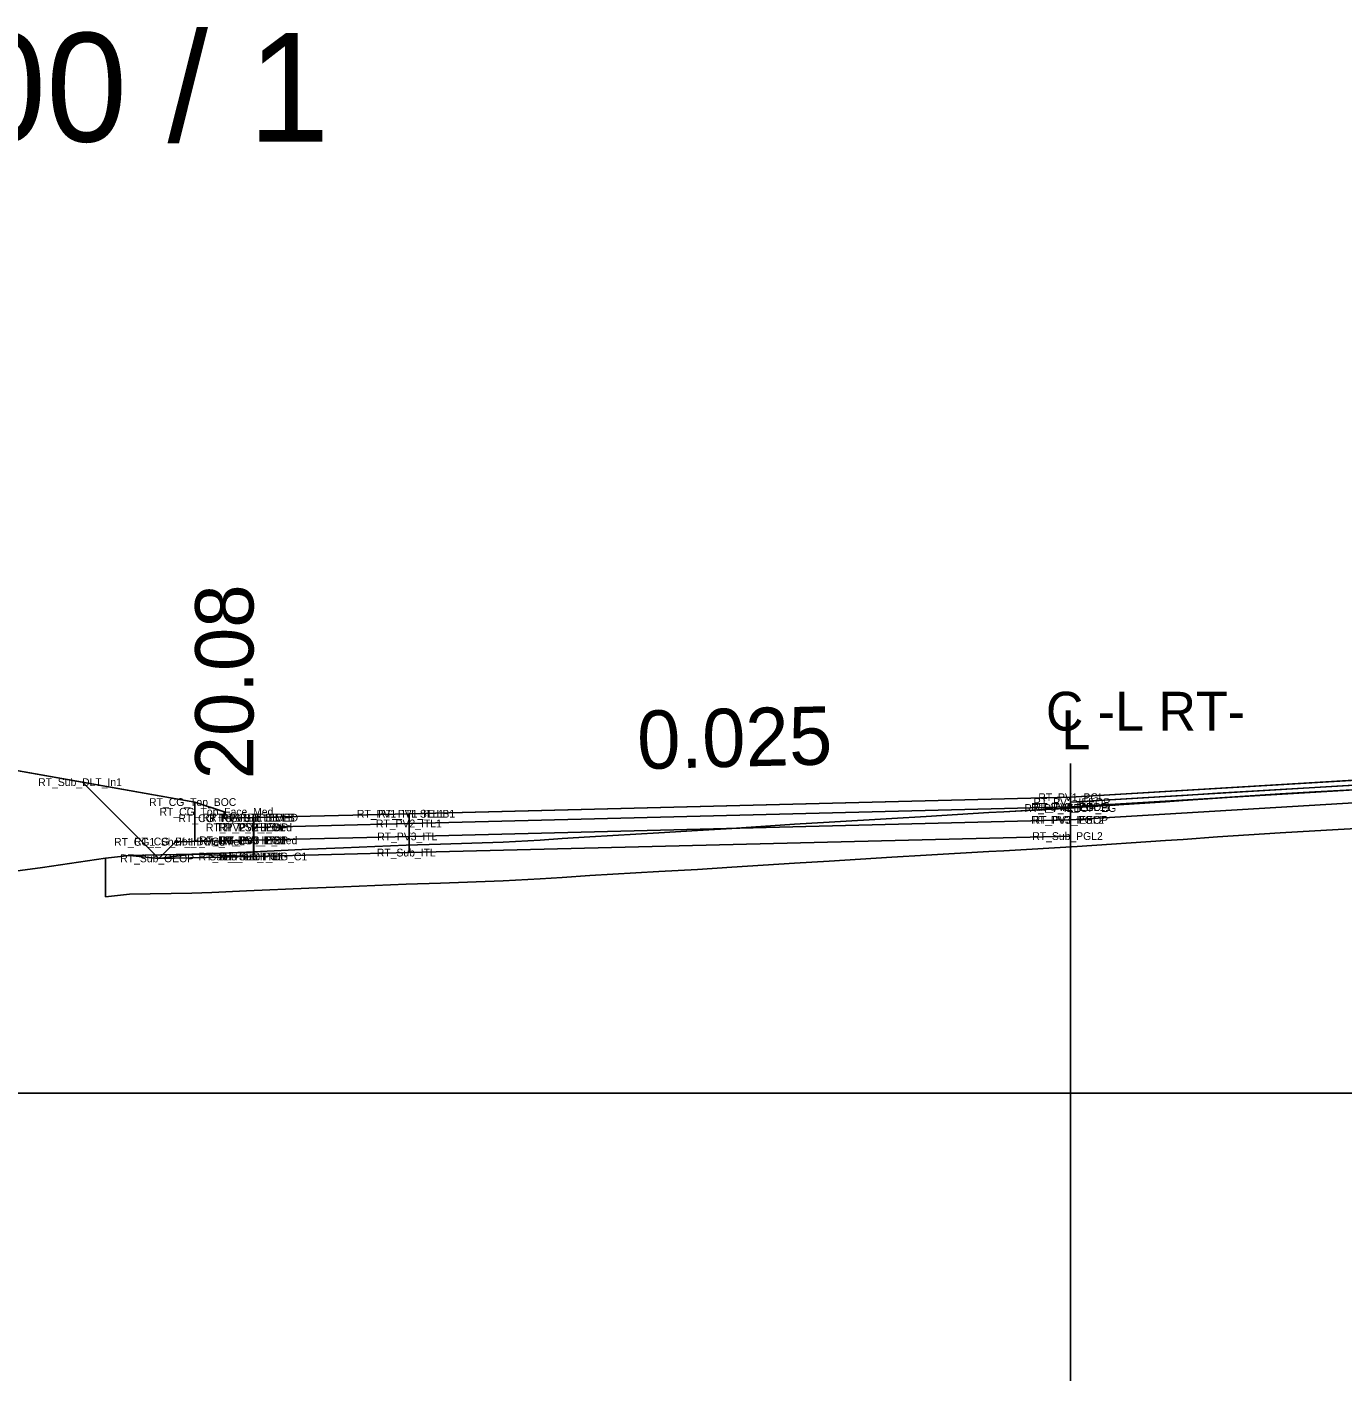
# Model space of a CAD drawing. Extents: x 2177029 to 2201446, y 59897 to 78390.
# Drawn here: x 2199245.88 to 2199279.74, y 69899.9 to 69934.76 of the extents above; entities that cross this region are included whole.
import ezdxf

# ---------------------------------------------------------------- set-up
doc = ezdxf.new("R2010")
doc.units = 0
for name, color, linetype in [('Exist CMT Pavement', 7, 'Continuous'), ('Exist Cross Section Cell', 7, 'Continuous'), ('Exist PHM Roadway Shape', 7, 'Continuous'), ('Exist XS Ground Line', 7, 'Continuous'), ('Old_Level_11', 7, 'Continuous'), ('Prop CMT Conc Surface', 7, 'Continuous'), ('Prop CMT Concrete Structures', 7, 'Continuous'), ('Prop CMT Guardrail Graphics', 7, 'Continuous'), ('Prop CMT Pvmt Course 1', 7, 'Continuous'), ('Prop CMT Pvmt Course 1 CG', 7, 'Continuous'), ('Prop CMT Pvmt Course 2', 7, 'Continuous'), ('Prop CMT Pvmt Course 2 CG', 7, 'Continuous'), ('Prop CMT Pvmt Course 3', 7, 'Continuous'), ('Prop CMT Pvmt Course 4', 7, 'Continuous'), ('Prop CMT Pvmt Surface', 7, 'Continuous'), ('Prop CMT Pvmt Wedge Surface 1', 7, 'Continuous'), ('Prop CMT Slope Grass', 7, 'Continuous'), ('Prop CMT Subgrade Earthwork', 7, 'Continuous'), ('Prop CMT Top Wall Envelope', 7, 'Continuous'), ('Prop Hatching', 7, 'Continuous'), ('Prop Horizontal Alignment', 7, 'Continuous'), ('Prop Retaining Wall', 7, 'Continuous'), ('Prop Terminator CELL', 7, 'Continuous'), ('Prop XS Side Slope Text', 7, 'Continuous'), ('Scratch_Level_0', 7, 'Continuous'), ('Scratch_Level_9', 7, 'Continuous')]:
    doc.layers.add(name, color=color, linetype=linetype)

msp = doc.modelspace()

# ---------------------------------------------------------------- linework, layer by layer
at = {"layer": 'Exist CMT Pavement'}
msp.add_line((2199272.732, 69899.904), (2199272.732, 69915.798), dxfattribs=at)
at = {"layer": 'Exist Cross Section Cell'}
msp.add_line((2199242.732, 69907.31), (2199442.732, 69907.31), dxfattribs=at)
at = {"layer": 'Exist XS Ground Line'}
msp.add_lwpolyline([(2199245.312, 69912.993), (2199246.277, 69913.12), (2199247.895, 69913.363), (2199248.517, 69913.432), (2199250.12, 69913.464), (2199250.631, 69913.479), (2199251.524, 69913.52), (2199253.131, 69913.59), (2199254.024, 69913.626), (2199255.631, 69913.695), (2199256.522, 69913.723), (2199258.131, 69913.776), (2199259.087, 69913.829), (2199259.651, 69913.866), (2199260.358, 69913.912), (2199262.138, 69914.015), (2199263.131, 69914.071), (2199264.021, 69914.129), (2199265.631, 69914.234), (2199266.52, 69914.287), (2199268.131, 69914.385), (2199269.02, 69914.438), (2199270.631, 69914.534), (2199271.019, 69914.555), (2199272.907, 69914.664), (2199275.174, 69914.816), (2199275.631, 69914.847), (2199276.518, 69914.908), (2199278.131, 69915.018), (2199279.017, 69915.067), (2199280.631, 69915.154)], dxfattribs=at)
at = {"layer": 'Prop CMT Conc Surface'}
for points in [[(2199272.732, 69914.806), (2199308.732, 69916.966)], [(2199272.732, 69914.931), (2199272.732, 69914.681), (2199272.732, 69914.681), (2199272.732, 69914.806)]]:
    msp.add_lwpolyline(points, dxfattribs=at)
at = {"layer": 'Prop CMT Concrete Structures'}
for p, q in [((2199272.732, 69914.931), (2199308.732, 69917.091)), ((2199272.732, 69914.931), (2199255.717, 69914.506)), ((2199251.707, 69914.406), (2199251.705, 69914.406)), ((2199251.715, 69914.406), (2199251.707, 69914.406)), ((2199255.717, 69914.506), (2199255.715, 69914.506))]:
    msp.add_line(p, q, dxfattribs=at)
at = {"layer": 'Prop CMT Guardrail Graphics'}
for points in [[(2199272.732, 69914.348), (2199308.732, 69916.508)], [(2199272.732, 69914.931), (2199272.732, 69914.348)]]:
    msp.add_lwpolyline(points, dxfattribs=at)
at = {"layer": 'Prop CMT Pvmt Course 1'}
for points in [[(2199272.732, 69914.681), (2199272.907, 69914.692), (2199275.174, 69914.828), (2199275.631, 69914.855), (2199276.518, 69914.909), (2199276.574, 69914.912)], [(2199276.574, 69914.912), (2199276.518, 69914.908), (2199275.631, 69914.847), (2199275.174, 69914.816), (2199272.907, 69914.664), (2199272.732, 69914.654)], [(2199272.732, 69914.654), (2199272.732, 69914.681)]]:
    msp.add_lwpolyline(points, dxfattribs=at)
at = {"layer": 'Prop CMT Pvmt Course 1 CG'}
for points in [[(2199251.715, 69913.822), (2199255.715, 69913.922)], [(2199255.715, 69913.922), (2199255.715, 69913.506)], [(2199251.715, 69913.406), (2199251.715, 69913.822)], [(2199255.715, 69913.506), (2199251.715, 69913.406)]]:
    msp.add_lwpolyline(points, dxfattribs=at)
at = {"layer": 'Prop CMT Pvmt Course 2'}
for points in [[(2199272.732, 69914.348), (2199255.715, 69913.922)], [(2199272.732, 69913.931), (2199272.732, 69914.348)], [(2199255.715, 69913.506), (2199272.732, 69913.931)], [(2199255.715, 69913.922), (2199255.715, 69913.506)], [(2199251.715, 69913.822), (2199251.705, 69913.822)], [(2199251.705, 69913.822), (2199251.705, 69913.406)], [(2199251.715, 69913.406), (2199251.715, 69913.822)], [(2199251.705, 69913.406), (2199251.715, 69913.406)]]:
    msp.add_lwpolyline(points, dxfattribs=at)
at = {"layer": 'Prop CMT Pvmt Course 2 CG'}
for points in [[(2199272.732, 69914.931), (2199308.732, 69917.091)], [(2199308.732, 69916.966), (2199272.732, 69914.806)], [(2199272.732, 69914.931), (2199255.715, 69914.506)], [(2199272.732, 69914.681), (2199272.732, 69914.931)], [(2199272.732, 69914.681), (2199272.732, 69914.931)], [(2199255.715, 69914.256), (2199272.732, 69914.681)], [(2199272.732, 69914.806), (2199272.732, 69914.681), (2199272.732, 69914.681)], [(2199251.715, 69914.406), (2199251.705, 69914.406)], [(2199251.705, 69914.406), (2199251.705, 69914.156)], [(2199251.715, 69914.156), (2199251.715, 69914.406)], [(2199255.715, 69914.506), (2199255.715, 69914.256)], [(2199251.705, 69914.156), (2199251.715, 69914.156)]]:
    msp.add_lwpolyline(points, dxfattribs=at)
at = {"layer": 'Prop CMT Pvmt Course 3'}
msp.add_line((2199272.732, 69914.654), (2199272.732, 69913.931), dxfattribs=at)
for points in [[(2199247.308, 69915.319), (2199249.27, 69913.357)], [(2199255.715, 69913.506), (2199272.732, 69913.931)], [(2199251.705, 69913.406), (2199249.27, 69913.357)], [(2199251.715, 69913.406), (2199251.705, 69913.406)], [(2199251.705, 69913.406), (2199251.705, 69913.406)], [(2199255.715, 69913.506), (2199251.715, 69913.406)]]:
    msp.add_lwpolyline(points, dxfattribs=at)
at = {"layer": 'Prop CMT Pvmt Course 4'}
msp.add_lwpolyline([(2199255.715, 69914.506), (2199251.715, 69914.406)], dxfattribs=at)
at = {"layer": 'Prop CMT Pvmt Surface'}
for points in [[(2199272.732, 69914.806), (2199272.907, 69914.817), (2199275.174, 69914.953), (2199275.631, 69914.98), (2199276.518, 69915.034), (2199278.131, 69915.13), (2199279.017, 69915.184), (2199280.631, 69915.28)], [(2199280.47, 69915.146), (2199279.017, 69915.067), (2199278.131, 69915.018), (2199276.574, 69914.912), (2199276.518, 69914.909), (2199275.631, 69914.855), (2199275.174, 69914.828), (2199272.907, 69914.692), (2199272.732, 69914.681)], [(2199272.732, 69914.681), (2199272.732, 69914.806)]]:
    msp.add_lwpolyline(points, dxfattribs=at)
at = {"layer": 'Prop CMT Pvmt Wedge Surface 1'}
for p, q in [((2199275.631, 69913.847), (2199276.518, 69913.908)), ((2199276.518, 69913.908), (2199278.131, 69914.018)), ((2199278.131, 69914.018), (2199279.017, 69914.067)), ((2199279.017, 69914.067), (2199280.631, 69914.154)), ((2199269.02, 69913.438), (2199270.631, 69913.534)), ((2199270.631, 69913.534), (2199271.019, 69913.555)), ((2199271.019, 69913.555), (2199272.907, 69913.664)), ((2199272.907, 69913.664), (2199275.174, 69913.816)), ((2199275.174, 69913.816), (2199275.631, 69913.847)), ((2199247.895, 69912.363), (2199247.895, 69913.363)), ((2199264.021, 69913.129), (2199265.631, 69913.234)), ((2199265.631, 69913.234), (2199266.52, 69913.287)), ((2199266.52, 69913.287), (2199268.131, 69913.385)), ((2199268.131, 69913.385), (2199269.02, 69913.438)), ((2199259.087, 69912.829), (2199259.651, 69912.866)), ((2199259.651, 69912.866), (2199260.358, 69912.912)), ((2199260.358, 69912.912), (2199262.138, 69913.015)), ((2199262.138, 69913.015), (2199263.131, 69913.071)), ((2199263.131, 69913.071), (2199264.021, 69913.129)), ((2199250.631, 69912.479), (2199251.524, 69912.52)), ((2199251.524, 69912.52), (2199253.131, 69912.59)), ((2199253.131, 69912.59), (2199254.024, 69912.626)), ((2199254.024, 69912.626), (2199255.631, 69912.695)), ((2199255.631, 69912.695), (2199256.522, 69912.723)), ((2199256.522, 69912.723), (2199258.131, 69912.776)), ((2199258.131, 69912.776), (2199259.087, 69912.829)), ((2199247.895, 69912.363), (2199248.517, 69912.432)), ((2199248.517, 69912.432), (2199250.12, 69912.464)), ((2199250.12, 69912.464), (2199250.631, 69912.479))]:
    msp.add_line(p, q, dxfattribs=at)
at = {"layer": 'Prop CMT Slope Grass'}
for points in [[(2199272.732, 69914.681), (2199255.715, 69914.256)], [(2199272.732, 69914.348), (2199272.732, 69914.681)], [(2199255.715, 69913.922), (2199272.732, 69914.348)], [(2199255.715, 69914.256), (2199255.715, 69913.922)], [(2199251.715, 69914.156), (2199251.705, 69914.156)], [(2199251.705, 69914.156), (2199251.705, 69913.822)], [(2199251.715, 69913.822), (2199251.715, 69914.156)], [(2199251.705, 69913.822), (2199251.715, 69913.822)]]:
    msp.add_lwpolyline(points, dxfattribs=at)
at = {"layer": 'Prop CMT Subgrade Earthwork'}
for points in [[(2199272.732, 69914.681), (2199308.732, 69916.841)], [(2199272.732, 69914.931), (2199272.732, 69914.681)]]:
    msp.add_lwpolyline(points, dxfattribs=at)
at = {"layer": 'Prop Hatching'}
msp.add_lwpolyline([(2199250.195, 69914.807), (2199242.846, 69916.111)], dxfattribs=at)
at = {"layer": 'Prop Horizontal Alignment'}
for points in [[(2199251.705, 69913.822), (2199249.695, 69913.782), (2199249.27, 69913.357)], [(2199251.705, 69913.406), (2199251.705, 69913.822)], [(2199249.27, 69913.357), (2199251.705, 69913.406)]]:
    msp.add_lwpolyline(points, dxfattribs=at)
at = {"layer": 'Prop Retaining Wall'}
msp.add_lwpolyline([(2199251.705, 69914.406), (2199250.956, 69914.391), (2199250.954, 69914.557), (2199250.195, 69914.807)], dxfattribs=at)
at = {"layer": 'Prop Terminator CELL'}
for points in [[(2199251.705, 69914.406), (2199250.956, 69914.391), (2199250.954, 69914.557), (2199250.195, 69914.807)], [(2199250.195, 69914.807), (2199250.195, 69913.792)], [(2199251.705, 69913.822), (2199251.705, 69914.406)], [(2199250.195, 69913.792), (2199251.705, 69913.822)]]:
    msp.add_lwpolyline(points, dxfattribs=at)
at = {"layer": 'Prop XS Side Slope Text'}
msp.add_lwpolyline([(2199308.741, 69917.092), (2199272.732, 69914.931), (2199255.715, 69914.506), (2199251.715, 69914.406), (2199250.956, 69914.391), (2199250.954, 69914.557), (2199250.195, 69914.807), (2199247.307, 69915.32), (2199249.27, 69913.357), (2199250.12, 69913.464), (2199250.631, 69913.479), (2199251.524, 69913.52), (2199253.131, 69913.59), (2199254.024, 69913.626), (2199255.631, 69913.695), (2199256.522, 69913.723), (2199258.131, 69913.776), (2199259.087, 69913.829), (2199259.651, 69913.866), (2199260.358, 69913.912), (2199262.138, 69914.015), (2199263.131, 69914.071), (2199264.021, 69914.129), (2199265.631, 69914.234), (2199266.52, 69914.287), (2199268.131, 69914.385), (2199269.02, 69914.438), (2199270.631, 69914.534), (2199271.019, 69914.555), (2199272.732, 69914.654), (2199272.907, 69914.664), (2199275.174, 69914.816), (2199275.631, 69914.847), (2199276.518, 69914.908), (2199278.131, 69915.018), (2199279.017, 69915.067), (2199280.631, 69915.154)], dxfattribs=at)
for points in [[(2199248.517, 69913.432), (2199249.27, 69913.357), (2199247.307, 69915.32), (2199242.846, 69916.111), (2199242.732, 69916.109), (2199242.732, 69912.813), (2199245.312, 69912.993), (2199246.277, 69913.12), (2199247.895, 69913.363)], [(2199255.715, 69913.506), (2199251.715, 69913.406), (2199250.12, 69913.464), (2199250.631, 69913.479), (2199251.524, 69913.52), (2199253.131, 69913.59), (2199254.024, 69913.626), (2199255.631, 69913.695), (2199256.522, 69913.723), (2199258.131, 69913.776), (2199259.087, 69913.829), (2199259.651, 69913.866), (2199260.358, 69913.912), (2199262.138, 69914.015), (2199263.131, 69914.071), (2199264.021, 69914.129), (2199265.631, 69914.234), (2199266.52, 69914.287), (2199268.131, 69914.385), (2199269.02, 69914.438), (2199270.631, 69914.534), (2199271.019, 69914.555), (2199272.732, 69914.654), (2199272.732, 69913.931)]]:
    msp.add_lwpolyline(points, close=True, dxfattribs=at)
at = {"layer": 'Scratch_Level_0'}
for points in [[(2199255.715, 69914.256), (2199251.715, 69914.156)], [(2199255.715, 69913.922), (2199255.715, 69914.256)], [(2199251.715, 69914.156), (2199251.715, 69913.822)], [(2199251.715, 69913.822), (2199255.715, 69913.922)]]:
    msp.add_lwpolyline(points, dxfattribs=at)
at = {"layer": 'Scratch_Level_9'}
for points in [[(2199255.715, 69914.506), (2199251.715, 69914.406)], [(2199251.715, 69914.406), (2199251.715, 69914.156)], [(2199251.715, 69914.156), (2199255.715, 69914.256)], [(2199255.715, 69914.256), (2199255.715, 69914.506)]]:
    msp.add_lwpolyline(points, dxfattribs=at)

# ---------------------------------------------------------------- texts
at = {"layer": 'Exist CMT Pavement'}
for s, p in [('C -L RT-', (2199272.099, 69916.646)), ('L', (2199272.502, 69916.165))]:
    msp.add_text(s, height=1, dxfattribs=at).set_placement(p)
at = {"layer": 'Exist Cross Section Cell'}
msp.add_text('39+00.00 / 1', height=2.8, dxfattribs=at).set_placement((2199232.732, 69931.809))
at = {"layer": 'Exist PHM Roadway Shape'}
for s, p in [('RT_Sub_DLT_In1', (2199246.165, 69915.219)), ('RT_PV1_PGL', (2199271.905, 69914.831)), ('RT_CG_Top_BOC', (2199249.019, 69914.707)), ('RT_CG_Top_Face_Med', (2199249.287, 69914.457)), ('RT_PV1_ITL SE LB1', (2199254.367, 69914.406)), ('RT_PV1_ITL1', (2199254.914, 69914.406)), ('RT_PV_IEEOP_EG', (2199271.546, 69914.553)), ('RT_PV2_IEEOP', (2199271.723, 69914.581)), ('RT_PV1_IEEOP', (2199271.779, 69914.706)), ('RT_PV2_PGL11', (2199271.782, 69914.581)), ('RT_CG_Top_Gut', (2199249.775, 69914.291)), ('RT_PV1_ITL SE LB', (2199250.39, 69914.306)), ('RT_PV2_ITL_med', (2199250.483, 69914.056)), ('RT_PV1_ITL_MED', (2199250.564, 69914.306)), ('RT_PS2_IEOP', (2199250.799, 69914.056)), ('RT_PV2_PGL', (2199250.832, 69914.056)), ('RT_PS1_IEOP', (2199250.856, 69914.306)), ('RT_PV2_ITL1', (2199254.857, 69914.156)), ('RT_PV3_IEEOP', (2199271.723, 69914.248)), ('RT_PV3_PGL2', (2199271.759, 69914.248)), ('RT_CG1_Shelf_In_Med', (2199248.119, 69913.682)), ('RT_CG_Bot_BOC_Med', (2199248.633, 69913.692)), ('RT_CG_Bot_IE_Med', (2199250.307, 69913.722)), ('RT_PS3_IEOP', (2199250.799, 69913.722)), ('RT_PV3_PGL', (2199250.832, 69913.722)), ('RT_PV3_ITL1', (2199250.847, 69913.722)), ('RT_PV3_ITL', (2199254.89, 69913.822)), ('RT_Sub_PGL2', (2199271.749, 69913.831)), ('RT_Sub_ITL', (2199254.88, 69913.406)), ('RT_Sub_OEOP', (2199248.276, 69913.257)), ('RT_Sub_IEOT_CG_C1', (2199250.293, 69913.306)), ('Sub_Trench_In', (2199250.567, 69913.306)), ('RT_Sub_PGL', (2199250.822, 69913.306)), ('RT_Sub_ITL1', (2199250.838, 69913.306))]:
    msp.add_text(s, height=0.2, dxfattribs=at).set_placement(p)
at = {"layer": 'Old_Level_11'}
msp.add_text('0.025', height=1.5, rotation=1.4307, dxfattribs=at).set_placement((2199261.598, 69915.654))
at = {"layer": 'Prop CMT Top Wall Envelope'}
msp.add_text('20.08', height=1.5, rotation=90, dxfattribs=at).set_placement((2199251.706, 69915.391))

doc.saveas('drawing.dxf')
